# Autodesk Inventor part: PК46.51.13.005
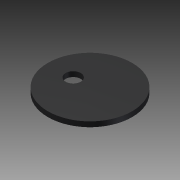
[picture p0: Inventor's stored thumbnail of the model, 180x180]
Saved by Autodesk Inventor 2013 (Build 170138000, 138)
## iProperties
Created: 2005-04
Part Number: PК46.51.13.005
Material: Silicone
Document SubType Name: Sheet Metal
Designer: =<Author>
Manufacturer: Standard
Standards Organization: Custom
Description: washer
Density: 1.25 g/cm^3
Sheet Metal Rule: Default
Mass: 7.12454 g
Surface Area: 43.5582 cm^2
Volume: 5.69963 cm^3
Author: PVitaliy
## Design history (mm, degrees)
node "Грань1"
body "Solid1"
sketch "Эскиз1"
  geometry: L1 (0, 0)-(-10, 0); C1 r 25 at (0, 0); C2 r 4.5 at (-10, 0)
  constraints: 2 centre point, 2 end point, 1 coincident, 1 horizontal, 1 other
  dimensions: "d4" = 50 diameter of C1; "d5" = 9 diameter of C2; "d6" = 10 distance of L1.start L1.end
feature "Плакирование1" dims "Thickness" = 3
other parameters: "BendRadius" = 3 (= Thickness), "BendReliefWidth" = 3 (= Thickness), "BendReliefDepth" = 1.5 (= 0.5 x Thickness), "CornerReliefSize" = 12 (= 4 x Thickness), "SeamGap" = 0.01, "MinimumRemnant" = 6 (= 2 x Thickness), "TransitionRadius" = 3 (= BendRadius), "d3" = 3 (= BendRadius), "JacobiRadiusSize" = 3 (= Thickness), "GapSize" = 3 (= Thickness)
